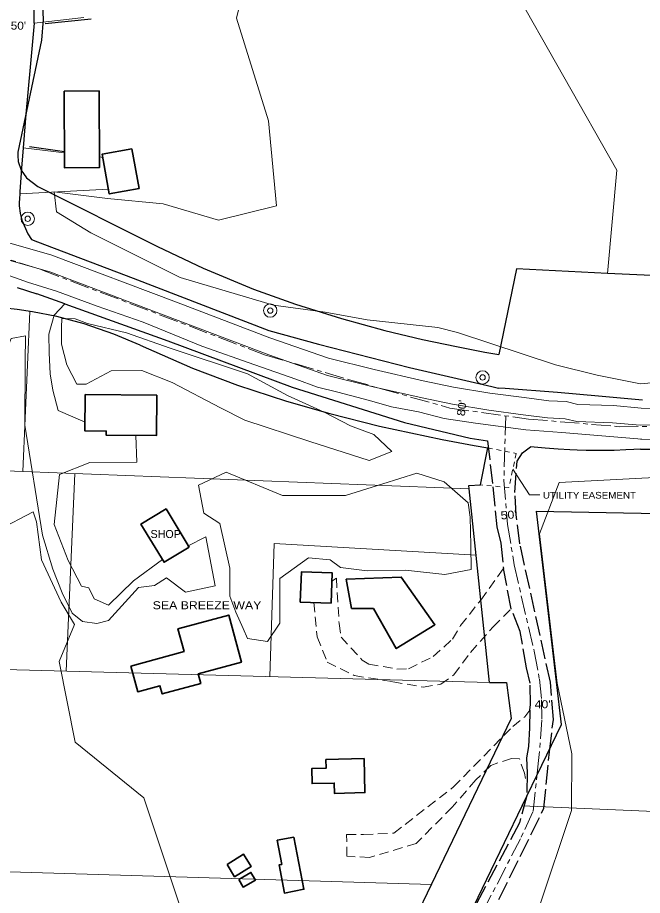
# Model space of a CAD drawing. Extents: x -861682 to -858969, y -1797841 to -1795153.
# Drawn here: x -860013 to -859544, y -1796801 to -1796143 of the extents above; entities that cross this region are included whole.
import ezdxf

# ---------------------------------------------------------------- set-up
doc = ezdxf.new("R2010")
doc.units = 0
doc.header["$LTSCALE"] = 2.4
for name, pattern in [('LONG_DASH_SHORT_DASH', [9.9, 6, -1.2, 1.5, -1.2]), ('LONG_DASHED', [7.5, 6, -1.5]), ('MEDIUM_DASHED', [4.5, 3, -1.5]), ('SHORT_DASHED', [2.7, 1.5, -1.2])]:
    doc.linetypes.add(name, pattern=pattern)
for name, color, linetype, lineweight in [('10', 7, 'Continuous', 25), ('11', 7, 'Continuous', 13), ('12', 7, 'Continuous', 35), ('14', 7, 'Continuous', 25), ('18', 7, 'Continuous', 13), ('30', 7, 'Continuous', 13), ('31', 7, 'Continuous', 13), ('32', 7, 'LONG_DASH_SHORT_DASH', 13), ('42', 7, 'Continuous', 25), ('46', 7, 'Continuous', 13), ('47', 7, 'SHORT_DASHED', 13), ('54', 7, 'Continuous', 13)]:
    doc.layers.add(name, color=color, linetype=linetype, lineweight=lineweight)
doc.layers.add('43', color=7, linetype='Continuous')

msp = doc.modelspace()

# ---------------------------------------------------------------- linework, layer by layer
at = {"layer": '10'}
for p, q in [((-860011.409, -1796275.072), (-860011.663, -1796278.59)), ((-860013.263, -1796345.31), (-859998.682, -1796350.09)), ((-859977.466, -1796357.694), (-859998.682, -1796350.09))]:
    msp.add_line(p, q, dxfattribs=at)
at = {"layer": '10', "linetype": 'LONG_DASHED'}
msp.add_line((-859642.872, -1796586.404), (-859648.604, -1796556.145), dxfattribs=at)
at = {"layer": '10'}
for points in [[(-860000.524, -1796147.349), (-860000.544, -1796144.044), (-860000.65, -1796138.535), (-860000.844, -1796133.028), (-860001.194, -1796126.426), (-860001.764, -1796118.733), (-860002.141, -1796114.955)], [(-860000.524, -1796147.349), (-860003.643, -1796180.262), (-860006.731, -1796215.39), (-860008.755, -1796240.601)], [(-860008.755, -1796240.601), (-860009.995, -1796256.033), (-860011.303, -1796273.603), (-860011.409, -1796275.072)], [(-860011.663, -1796278.59), (-860011.779, -1796281.894), (-860011.725, -1796284.097), (-860011.132, -1796289.572), (-860009.893, -1796294.937), (-860005.409, -1796305.299), (-860002.652, -1796309.466)], [(-860002.652, -1796309.466), (-859997.978, -1796311.242), (-859926.445, -1796338.506), (-859824.599, -1796377.617)], [(-859977.466, -1796357.694), (-859900.298, -1796385.357), (-859807.11, -1796420.172), (-859722.931, -1796446.522), (-859673.526, -1796458.368), (-859660.719, -1796460.286)], [(-859824.599, -1796377.617), (-859787.441, -1796387.961), (-859719.128, -1796405.49), (-859657.321, -1796419.715), (-859652.435, -1796420.774)], [(-859544.46, -1796429.897), (-859577.379, -1796426.85), (-859608.122, -1796424.215), (-859647.448, -1796421.141), (-859652.435, -1796420.774)], [(-859545.936, -1796466.512), (-859538.224, -1796466.652), (-859531.612, -1796466.726), (-859527.204, -1796466.751), (-859523.898, -1796466.757), (-859522.796, -1796466.757), (-859518.388, -1796466.743), (-859511.777, -1796466.687), (-859505.165, -1796466.587), (-859495.25, -1796466.355), (-859485.338, -1796466.026), (-859474.328, -1796465.545), (-859463.325, -1796464.944), (-859450.13, -1796464.064), (-859436.948, -1796463.01), (-859412.35, -1796460.576), (-859407.383, -1796460.011)], [(-859545.936, -1796466.511), (-859550.925, -1796466.848), (-859556.932, -1796467.178), (-859565.742, -1796467.514), (-859571.251, -1796467.635), (-859575.658, -1796467.683), (-859577.862, -1796467.69), (-859578.964, -1796467.69), (-859583.372, -1796467.661), (-859586.678, -1796467.61), (-859593.287, -1796467.435), (-859598.793, -1796467.214), (-859607.595, -1796466.719), (-859617.483, -1796465.952), (-859628.446, -1796464.842)]]:
    msp.add_lwpolyline(points, dxfattribs=at)
at = {"layer": '10', "linetype": 'LONG_DASHED'}
for points in [[(-859660.719, -1796460.286), (-859656.612, -1796494.906), (-859653.723, -1796524.785), (-859650.595, -1796537.054), (-859648.869, -1796554.75), (-859648.604, -1796556.145)], [(-859668.064, -1796836.421), (-859618.333, -1796735.875), (-859614.251, -1796693.585), (-859611.278, -1796669.249), (-859613.515, -1796641.39), (-859636.367, -1796537.57), (-859639.052, -1796515.854), (-859640.064, -1796499.091), (-859638.504, -1796475.704), (-859634.279, -1796469.311), (-859628.446, -1796464.842)], [(-859628.935, -1796662.366), (-859628.342, -1796657.942), (-859628.628, -1796641.923), (-859631.507, -1796630.599), (-859636.104, -1796603.223), (-859642.872, -1796586.404)], [(-859628.935, -1796662.366), (-859629.064, -1796675.624), (-859629.786, -1796689.577), (-859631.349, -1796697.997), (-859630.873, -1796709.492), (-859631.124, -1796726.244), (-859636.709, -1796746.812), (-859682.764, -1796832.89)]]:
    msp.add_lwpolyline(points, dxfattribs=at)
at = {"layer": '11'}
for p, q in [((-859963.454, -1796143.063), (-860000.524, -1796147.349)), ((-859977.89, -1796244.355), (-860008.755, -1796240.601)), ((-859951.632, -1796247.549), (-859949.271, -1796247.836)), ((-859944.891, -1796271.686), (-860011.409, -1796275.072))]:
    msp.add_line(p, q, dxfattribs=at)
for points in [[(-859962.435, -1796446.494), (-859982.509, -1796437.642), (-859986.585, -1796422.308), (-859988.524, -1796410.035), (-859989.295, -1796394.451), (-859989.588, -1796380.283), (-859985.63, -1796366.097), (-859977.466, -1796357.694)], [(-859885.594, -1796539.373), (-859871.84, -1796532.369), (-859864.843, -1796569.183), (-859887.024, -1796573.759), (-859901.474, -1796562.953), (-859910.424, -1796568.893), (-859922.463, -1796570.358), (-859944.799, -1796595.009), (-859953.476, -1796597.318), (-859964.301, -1796595.874), (-859972, -1796589.619), (-859979.698, -1796574.223), (-859986.674, -1796556.541), (-859994.373, -1796531.16), (-860007.497, -1796448.604), (-860007.451, -1796401.371), (-860007.058, -1796381.532), (-860017.913, -1796383.701), (-860024.457, -1796400.731), (-860024.45, -1796402.445)], [(-859904.451, -1796549.275), (-859926.025, -1796565.413), (-859944.845, -1796583.673), (-859955.492, -1796578.756), (-859959.539, -1796570.507), (-859965.212, -1796569.349), (-859974.972, -1796550.022), (-859985.707, -1796523.143), (-859981.607, -1796485.576), (-859958.735, -1796476.511), (-859923.548, -1796476.37), (-859924.343, -1796456.343)]]:
    msp.add_lwpolyline(points, dxfattribs=at)
at = {"layer": '11', "linetype": 'MEDIUM_DASHED'}
for points in [[(-859777.276, -1796565.568), (-859773.945, -1796563.389), (-859771.92, -1796597.388), (-859770.462, -1796607.537), (-859754.57, -1796624.714), (-859749.599, -1796627.764), (-859728.565, -1796631.458), (-859719.829, -1796631.187), (-859701.444, -1796622.139), (-859686.854, -1796609.092), (-859680.991, -1796598.913), (-859665.718, -1796579.724), (-859648.604, -1796556.145)], [(-859790.758, -1796581.584), (-859788.411, -1796607.373), (-859780.778, -1796626.236), (-859760.664, -1796636.31), (-859731.598, -1796640.917), (-859708.909, -1796645.077), (-859695.693, -1796642.898), (-859685.803, -1796635.774), (-859673.354, -1796618.957), (-859656.427, -1796599.76), (-859642.872, -1796586.404)], [(-859632.191, -1796713.394), (-859632.913, -1796709.544), (-859636.665, -1796698.869), (-859642.57, -1796698.421), (-859658.136, -1796703.679), (-859669.428, -1796714.587), (-859687.058, -1796734.967), (-859714.108, -1796762.235), (-859749.11, -1796772.695), (-859766.07, -1796771.853), (-859766.327, -1796755.595), (-859753.574, -1796755.544), (-859730.906, -1796754.508), (-859686.174, -1796719.849), (-859641.722, -1796674.566), (-859632.777, -1796667.209), (-859628.935, -1796662.366)]]:
    msp.add_lwpolyline(points, dxfattribs=at)
at = {"layer": '12'}
for points in [[(-859978.104, -1796198.192), (-859977.839, -1796255.609), (-859951.595, -1796255.488), (-859951.86, -1796198.071)], [(-859927.404, -1796241.435), (-859921.946, -1796271.161), (-859944.236, -1796275.254), (-859949.695, -1796245.528)], [(-859962.244, -1796425.748), (-859908.633, -1796426.242), (-859908.912, -1796456.485), (-859946.529, -1796456.138), (-859946.501, -1796453.08), (-859962.494, -1796452.933)], [(-859884.326, -1796539.976), (-859903.173, -1796551.387), (-859920.479, -1796522.804), (-859901.633, -1796511.393)], [(-859801.031, -1796581.206), (-859777.883, -1796582.058), (-859777.051, -1796559.44), (-859800.199, -1796558.589)], [(-859766.619, -1796564.064), (-859725.297, -1796562.482), (-859700.12, -1796598.277), (-859729.097, -1796616.106), (-859746.221, -1796585.946), (-859762.516, -1796586.011)], [(-859928.13, -1796629.184), (-859922.857, -1796648.528), (-859906.255, -1796644.002), (-859904.6, -1796650.073), (-859875.649, -1796642.181), (-859877.569, -1796635.139), (-859845.123, -1796626.293), (-859854.729, -1796591.059), (-859892.739, -1796601.422), (-859888.142, -1796618.283)], [(-859753.091, -1796698.623), (-859752.516, -1796724.126), (-859775.445, -1796724.643), (-859775.62, -1796716.888), (-859792.245, -1796717.263), (-859792.497, -1796706.102), (-859781.633, -1796705.857), (-859781.782, -1796699.271)], [(-859805.756, -1796757.402), (-859798.278, -1796796.575), (-859812.927, -1796799.372), (-859816.946, -1796778.322), (-859814.894, -1796777.93), (-859818.356, -1796759.809)], [(-859855.977, -1796777.914), (-859843.49, -1796770.306), (-859837.865, -1796779.538), (-859850.351, -1796787.146)], [(-859847.193, -1796789.214), (-859838.004, -1796783.982), (-859834.739, -1796789.716), (-859843.928, -1796794.948)]]:
    msp.add_lwpolyline(points, close=True, dxfattribs=at)
at = {"layer": '14'}
for p, q in [((-859992.449, -1796147.539), (-859957.745, -1796143.928)), ((-860003.97, -1796239.771), (-859977.895, -1796243.566))]:
    msp.add_line(p, q, dxfattribs=at)
at = {"layer": '18'}
for points in [[(-859545.868, -1796417.533), (-859578.32, -1796411.157), (-859609.58, -1796403.391), (-859683.043, -1796379.22), (-859697.964, -1796375.332), (-859750.944, -1796369.65), (-859782.423, -1796363.78), (-859821.22, -1796358.683), (-859891.108, -1796338.026), (-859933.117, -1796316.891), (-859958.037, -1796304.348), (-859983.93, -1796288.743), (-859985.48, -1796273.634), (-859945.596, -1796278.594), (-859903.879, -1796282.609), (-859862.419, -1796295.006), (-859818.799, -1796284.228), (-859824.791, -1796220.481), (-859848.857, -1796143.423), (-859830.375, -1796068.119)], [(-859347.215, -1796129.795), (-859321.586, -1796150.045), (-859299.228, -1796169.09), (-859292.462, -1796192.945), (-859295.557, -1796234.584), (-859300.563, -1796261.567), (-859301.495, -1796283.615), (-859305.463, -1796310.868), (-859319.613, -1796338.001), (-859337.091, -1796361.222), (-859367.474, -1796395.166), (-859401.932, -1796399.926), (-859462.09, -1796406.183), (-859502.465, -1796413.666), (-859545.868, -1796417.533)], [(-859174.444, -1796838.584), (-859160.301, -1796800.902), (-859133.044, -1796756.701), (-859150.148, -1796729.201), (-859157.395, -1796696.861), (-859185.418, -1796680.573), (-859231.56, -1796693.087), (-859269.626, -1796707.406), (-859297.15, -1796705.264), (-859348.866, -1796689.3), (-859371.409, -1796664.747), (-859375.928, -1796621.742), (-859391.791, -1796541.014), (-859432.003, -1796475.386), (-859474.387, -1796478.095), (-859520.89, -1796487.146), (-859606.996, -1796491.526), (-859621.543, -1796530.075), (-859608.431, -1796642.017), (-859597.331, -1796695.082), (-859597.645, -1796737.407), (-859622.316, -1796811.496)], [(-860027.255, -1796527.086), (-860001.229, -1796513.478), (-859998.944, -1796521.176), (-859995.094, -1796549.684), (-859980.42, -1796581.199), (-859970.436, -1796598.16), (-859981.752, -1796625.856), (-859969.938, -1796686.266), (-859918.287, -1796728.096), (-859891.994, -1796806.633)]]:
    msp.add_lwpolyline(points, dxfattribs=at)
for points in [[(-859960.571, -1796372.372), (-859931.259, -1796379.34), (-859898.622, -1796390.781), (-859840.685, -1796410.15), (-859810.627, -1796426.325), (-859783.182, -1796438.968), (-859763.304, -1796449.043), (-859745.801, -1796455.586), (-859732.289, -1796468.284), (-859749.265, -1796475.201), (-859793.957, -1796460.974), (-859842.671, -1796444.874), (-859860.893, -1796435.501), (-859897.102, -1796416.517), (-859919.809, -1796407.633), (-859942.952, -1796407.962), (-859961.569, -1796417.956), (-859968.654, -1796417.984), (-859976.033, -1796403.371), (-859980.111, -1796387.801), (-859980.16, -1796375.521), (-859979.715, -1796368.67), (-859969.795, -1796368.867)], [(-859849.414, -1796588.722), (-859853.949, -1796576.695), (-859853.797, -1796555.912), (-859861.252, -1796522.407), (-859873.327, -1796514.662), (-859877.426, -1796493.66), (-859856.683, -1796483.894), (-859814.339, -1796501.437), (-859767.108, -1796501.248), (-859739.039, -1796492.633), (-859713.566, -1796484.502), (-859693.23, -1796491.033), (-859675.218, -1796506.784), (-859673.758, -1796517.641), (-859673.201, -1796538.658), (-859672.892, -1796556.841), (-859692.715, -1796560.463), (-859722.012, -1796557.274), (-859750.822, -1796557.862), (-859770.906, -1796555.344), (-859778.723, -1796549.471), (-859794.787, -1796548.119), (-859816.452, -1796563.556), (-859816.408, -1796574.656), (-859816.318, -1796597.091), (-859825.709, -1796610.826), (-859840.597, -1796608.524), (-859843.933, -1796600.98)]]:
    msp.add_lwpolyline(points, close=True, dxfattribs=at)
at = {"layer": '30'}
for p, q in [((-860003.816, -1796363.287), (-860009.11, -1796483.248)), ((-860164.144, -1796477.6), (-860009.11, -1796483.248)), ((-859674.373, -1796496.253), (-860009.11, -1796483.248)), ((-859970.035, -1796484.766), (-859976.574, -1796632.935)), ((-859659.085, -1796641.503), (-860022.934, -1796631.684)), ((-859111.628, -1796756.635), (-859634.674, -1796733.987)), ((-859702.728, -1796792.888), (-860142.618, -1796779.921))]:
    msp.add_line(p, q, dxfattribs=at)
for points in [[(-859643.077, -1796117.35), (-859563.675, -1796257.477), (-859570.567, -1796334.872)], [(-859823.792, -1796637.058), (-859820.506, -1796537.245), (-859669.128, -1796546.082)]]:
    msp.add_lwpolyline(points, dxfattribs=at)
at = {"layer": '31'}
for centre, radius in [((-860005.387, -1796293.895), 5), ((-860005.387, -1796293.895), 2), ((-859823.547, -1796362.723), 5), ((-859823.547, -1796362.723), 2), ((-859664.319, -1796412.845), 5), ((-859664.319, -1796412.845), 2)]:
    msp.add_circle(centre, radius, dxfattribs=at)
at = {"layer": '32'}
for points in [[(-861651.105, -1796687.844), (-861333.558, -1796608.31), (-860734.009, -1796456.297), (-860402.78, -1796372.876), (-860279.286, -1796339.345), (-860213.04, -1796323.806), (-860166.423, -1796315.627), (-860126.348, -1796310.72), (-860089.545, -1796308.267), (-860056.831, -1796312.356), (-859995.492, -1796331.984), (-859827.834, -1796395.777), (-859764.042, -1796414.588), (-859688.8, -1796435.852), (-859629.915, -1796444.03), (-859562.034, -1796449.756), (-859471.253, -1796448.938), (-859395.193, -1796443.213), (-859240.62, -1796421.131), (-859002.083, -1796383.657)], [(-859646.986, -1796441.659), (-859648.32, -1796490.003), (-859645.563, -1796523.079), (-859640.663, -1796553.399), (-859625.656, -1796618.021), (-859621.675, -1796639.153), (-859620.144, -1796654.466), (-859619.837, -1796669.473), (-859622.287, -1796700.099), (-859626.531, -1796738.59), (-859635.941, -1796758.82), (-859675.317, -1796834.679)]]:
    msp.add_lwpolyline(points, dxfattribs=at)
at = {"layer": '42'}
for p, q in [((-859995.098, -1796160.007), (-860012.791, -1796244.064)), ((-859659.085, -1796641.503), (-859674.373, -1796496.253)), ((-859737.749, -1796947.769), (-859634.674, -1796733.987))]:
    msp.add_line(p, q, dxfattribs=at)
for points in [[(-859994.502, -1796129.729), (-859994.219, -1796133.946), (-859993.927, -1796144.571), (-859995.098, -1796160.007)], [(-860012.791, -1796244.064), (-860012.934, -1796246.342), (-860012.565, -1796250.873), (-860010.431, -1796257.361), (-860006.393, -1796263.304), (-859997.916, -1796269.666), (-859908.056, -1796314.608)], [(-859908.056, -1796314.608), (-859873.734, -1796330.998), (-859836.172, -1796346.565), (-859804.524, -1796357.963), (-859770.051, -1796368.774), (-859737.511, -1796377.607), (-859709.508, -1796384.282), (-859683.914, -1796389.757), (-859662.754, -1796393.877), (-859652.24, -1796395.731)], [(-859570.567, -1796334.872), (-859638.943, -1796331.36), (-859652.24, -1796395.731)], [(-859429.066, -1796363.089), (-859453.101, -1796366.438), (-859455.106, -1796340.157), (-859570.567, -1796334.872)], [(-859921.126, -1796388.728), (-859940.748, -1796380.277), (-859963.13, -1796372.557), (-859983.607, -1796367.145), (-860001.905, -1796363.562), (-860013.337, -1796361.916), (-860022.49, -1796360.947), (-860031.708, -1796360.316), (-860036.373, -1796360.145), (-860041.1, -1796360.079), (-860053.275, -1796360.417), (-860068.53, -1796361.752), (-860086.647, -1796364.344), (-860113.909, -1796370.012), (-860125.144, -1796372.987)], [(-859921.126, -1796388.728), (-859881.742, -1796405.805), (-859848.069, -1796418.526), (-859811.462, -1796430.608), (-859778.974, -1796439.948), (-859741.521, -1796449.291), (-859694.727, -1796459.242), (-859670.738, -1796463.834), (-859660.308, -1796465.706)], [(-859634.674, -1796733.987), (-859605.184, -1796673.009), (-859623.78, -1796512.972), (-859440.994, -1796516.569), (-859439.86, -1796496.911), (-859339.579, -1796497.084), (-859342.387, -1796467.857), (-859104.779, -1796435.814)], [(-859674.373, -1796496.253), (-859674.654, -1796493.826), (-859665.834, -1796493.431), (-859660.308, -1796465.706)], [(-859659.085, -1796641.503), (-859646.306, -1796641.548), (-859642.853, -1796668.529), (-859775.171, -1796943.35)]]:
    msp.add_lwpolyline(points, dxfattribs=at)
at = {"layer": '46'}
msp.add_lwpolyline([(-859621.366, -1796500.878), (-859629.132, -1796500.878), (-859641.67, -1796481.571)], dxfattribs=at)
at = {"layer": '47'}
msp.add_lwpolyline([(-859660.308, -1796465.706), (-859639.116, -1796469.816), (-859644.662, -1796495.331), (-859665.834, -1796493.431)], dxfattribs=at)
at = {"layer": '54'}
for points in [[(-859545.414, -1796435.904), (-859566.072, -1796433.962), (-859593.018, -1796433.015), (-859601.542, -1796430.963), (-859614.78, -1796430.37), (-859633.232, -1796427.932), (-859658.781, -1796424.611), (-859686.231, -1796420.125), (-859708.957, -1796415.361), (-859745.656, -1796406.939), (-859779.993, -1796398.496), (-859823.842, -1796383.047), (-859893.781, -1796356.484), (-859988.138, -1796320.918), (-860022.25, -1796311.056), (-860057.055, -1796303.09), (-860086.378, -1796300.51), (-860125.376, -1796299.434), (-860163.858, -1796303.314), (-860194.778, -1796307.365), (-860218.117, -1796313.477), (-860315.269, -1796336.538)], [(-859979.698, -1796337.212), (-859988.892, -1796333.747), (-860023.004, -1796323.885), (-860057.809, -1796315.919), (-860087.132, -1796313.339), (-860126.13, -1796312.263), (-860172.631, -1796317.253)], [(-859544.864, -1796459.109), (-859604.819, -1796454.078), (-859631.986, -1796452.062), (-859669.556, -1796447.017), (-859693.186, -1796443.569), (-859712.335, -1796438.686), (-859732.66, -1796434.989), (-859749.211, -1796430.095), (-859772.852, -1796423.813), (-859788.218, -1796420.096), (-859804.301, -1796414.02), (-859835.045, -1796403.28), (-859874.776, -1796389.505), (-859918.774, -1796371.497), (-859953.302, -1796359.355), (-859983.812, -1796348.141), (-860005.566, -1796341.38), (-860021.649, -1796335.54)], [(-859546.168, -1796448.733), (-859566.826, -1796446.791), (-859593.772, -1796445.844), (-859602.296, -1796443.792), (-859615.534, -1796443.199), (-859633.986, -1796440.761), (-859659.535, -1796437.44), (-859686.985, -1796432.954), (-859709.711, -1796428.19), (-859746.41, -1796419.768), (-859780.747, -1796411.325), (-859824.596, -1796395.876), (-859894.535, -1796369.313), (-859979.698, -1796337.212)], [(-859002.041, -1796381.842), (-859053.45, -1796390.181), (-859156.868, -1796405.745), (-859244.786, -1796419.699), (-859343.381, -1796434.293), (-859400.907, -1796442.299), (-859441.496, -1796446.496), (-859486.409, -1796447.753), (-859546.168, -1796448.733)], [(-859024.666, -1796396.369), (-859086.63, -1796405.988), (-859154.426, -1796417.212), (-859225.106, -1796428.135), (-859296.827, -1796439.137), (-859350.437, -1796446.328), (-859398.709, -1796453.199), (-859433.489, -1796457.311), (-859461.242, -1796459.332), (-859512.74, -1796459.733), (-859545.87, -1796459.101)], [(-859545.414, -1796435.904), (-859521.374, -1796436.478), (-859493.685, -1796436.802), (-859466.421, -1796436.687), (-859438.886, -1796434.239), (-859407.57, -1796430.899), (-859368.081, -1796425.396)]]:
    msp.add_lwpolyline(points, dxfattribs=at)

# ---------------------------------------------------------------- texts
at = {"layer": '43'}
for s, rotation, width, p in [("50'", 359.384, 1.1, (-860018.191, -1796152.051)), ("80'", 82.235, 1.15, (-859677.806, -1796442.115)), ("50'", 4.54, 1.15, (-859650.545, -1796519.362)), ("40'", 0.725, 1.15, (-859625.299, -1796660.944))]:
    msp.add_text(s, height=6, rotation=rotation, dxfattribs=dict(at, width=width)).set_placement(p)
at = {"layer": '46'}
msp.add_text('SHOP', height=6, dxfattribs=at).set_placement((-859913.329, -1796533.229))
at = {"layer": '46', "width": 1.15}
msp.add_text('SEA BREEZE WAY', height=6, dxfattribs=at).set_placement((-859911.734, -1796586.623))
at = {"layer": '47', "width": 1.1}
msp.add_text('UTILITY EASEMENT', height=5, dxfattribs=at).set_placement((-859619.147, -1796503.651))

doc.saveas('drawing.dxf')
